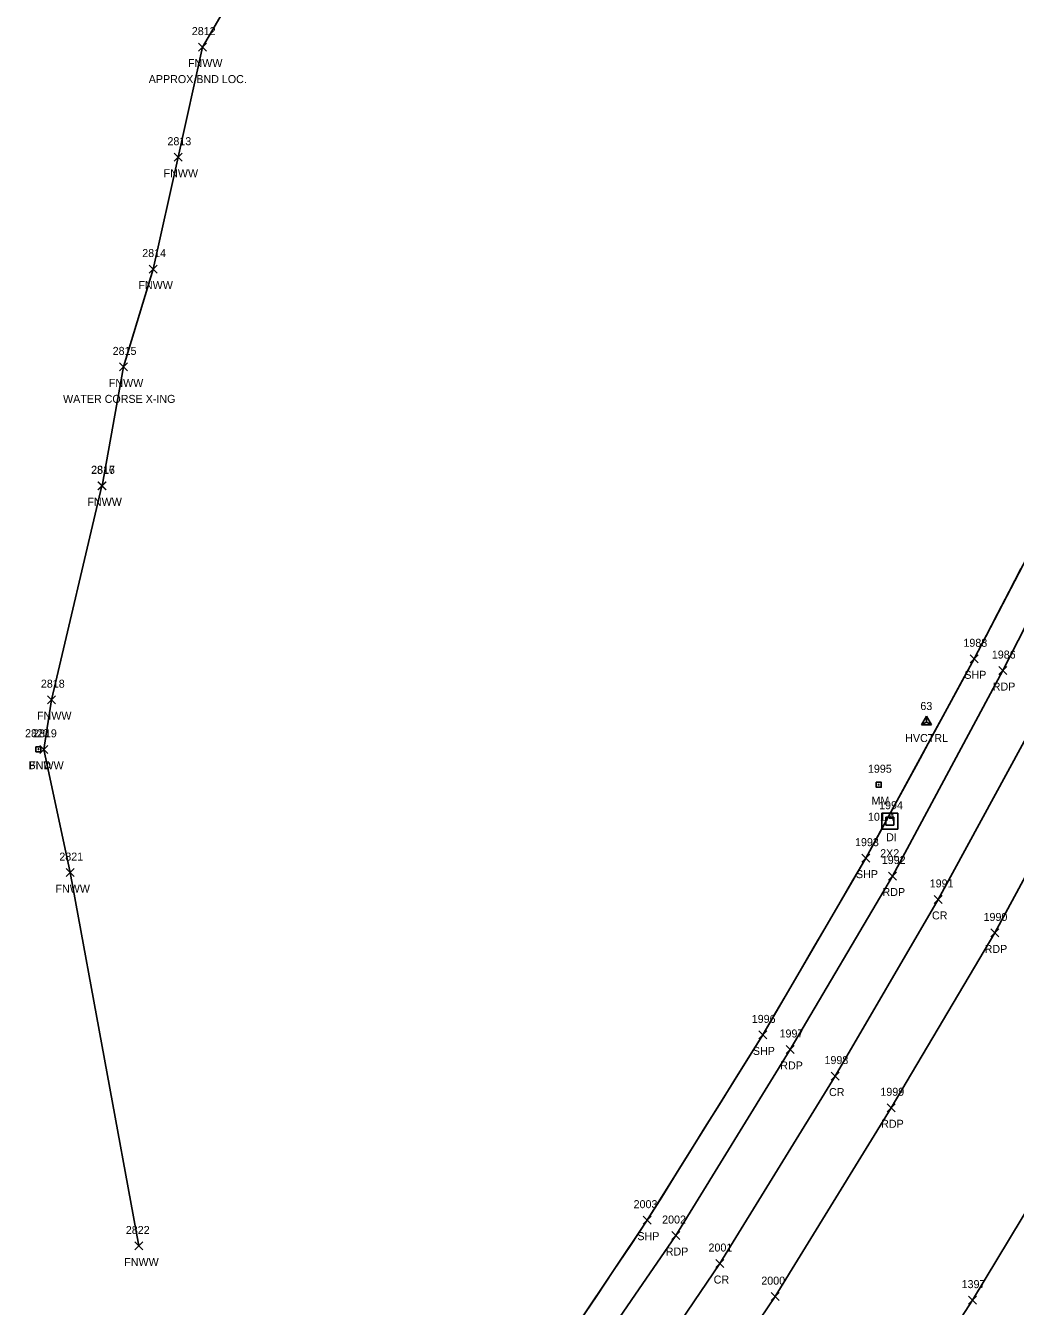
# Model space of a CAD drawing. Extents: x 1472022 to 1479249, y 777216 to 786527.
# Drawn here: x 1473093 to 1473340.4, y 778431.9 to 778752 of the extents above; entities that cross this region are included whole.
import ezdxf

# ---------------------------------------------------------------- set-up
doc = ezdxf.new("R2010")
doc.units = 0
for name, color, linetype in [('C_A', 7, 'Continuous'), ('C_I', 7, 'Continuous'), ('CPSM', 7, 'Continuous'), ('D_A', 7, 'Continuous'), ('D_C', 7, 'Continuous'), ('D_I', 7, 'Continuous'), ('DS', 7, 'Continuous'), ('L_A', 7, 'Continuous'), ('L_C', 7, 'Continuous'), ('L_I', 7, 'Continuous'), ('L_TIC', 7, 'Continuous'), ('Level 18', 7, 'Continuous'), ('LFNC', 7, 'Continuous'), ('LSOGP', 7, 'Continuous'), ('M_A', 7, 'Continuous'), ('M_I', 7, 'Continuous'), ('P_A', 7, 'Continuous'), ('P_I', 7, 'Continuous'), ('P_TIC', 7, 'Continuous'), ('PET', 7, 'Continuous'), ('PRC', 7, 'Continuous'), ('PSP', 7, 'Continuous'), ('S_A', 7, 'Continuous'), ('S_C', 7, 'Continuous'), ('S_I', 7, 'Continuous'), ('SRM', 7, 'Continuous')]:
    doc.layers.add(name, color=color, linetype=linetype)

msp = doc.modelspace()

# ---------------------------------------------------------------- linework, layer by layer
at = {"layer": 'CPSM'}
for p, q in [((1473316.9, 778577.24), (1473318.15, 778579.41)), ((1473319.4, 778577.24), (1473318.15, 778579.41)), ((1473318.15, 778577.96), (1473318.15, 778579.41)), ((1473316.9, 778577.24), (1473318.15, 778577.96)), ((1473316.9, 778577.24), (1473319.4, 778577.24)), ((1473318.15, 778577.96), (1473318.15, 778577.96)), ((1473318.15, 778577.96), (1473319.4, 778577.24))]:
    msp.add_line(p, q, dxfattribs=at)
at = {"layer": 'DS'}
for p, q in [((1473307.02, 778555.16), (1473311.02, 778555.16)), ((1473307.02, 778551.16), (1473307.02, 778555.16)), ((1473308.02, 778552.16), (1473308.02, 778554.16)), ((1473308.02, 778554.16), (1473310.02, 778554.16)), ((1473309.02, 778553.17), (1473309.02, 778553.17)), ((1473309.02, 778553.17), (1473309.02, 778553.17)), ((1473310.02, 778554.16), (1473310.02, 778552.16)), ((1473311.02, 778555.16), (1473311.02, 778551.16)), ((1473311.02, 778551.16), (1473307.02, 778551.16)), ((1473310.02, 778552.16), (1473308.02, 778552.16))]:
    msp.add_line(p, q, dxfattribs=at)
at = {"layer": 'L_TIC'}
for points in [[(1473136.27, 778745.63), (1473138.27, 778747.63)], [(1473138.27, 778745.63), (1473136.27, 778747.63)], [(1473130.18, 778718.11), (1473132.18, 778720.11)], [(1473132.18, 778718.11), (1473130.18, 778720.11)], [(1473123.89, 778690.16), (1473125.89, 778692.16)], [(1473125.89, 778690.16), (1473123.89, 778692.16)], [(1473116.49, 778665.71), (1473118.49, 778667.71)], [(1473118.49, 778665.71), (1473116.49, 778667.71)], [(1473111.13, 778636.02), (1473113.13, 778638.02)], [(1473113.13, 778636.02), (1473111.13, 778638.02)], [(1473111.14, 778635.96), (1473113.14, 778637.96)], [(1473113.14, 778635.96), (1473111.14, 778637.96)], [(1473098.55, 778582.54), (1473100.55, 778584.54)], [(1473100.55, 778582.54), (1473098.55, 778584.54)], [(1473096.59, 778570.13), (1473098.59, 778572.13)], [(1473098.59, 778570.13), (1473096.59, 778572.13)], [(1473103.16, 778539.32), (1473105.16, 778541.32)], [(1473105.16, 778539.32), (1473103.16, 778541.32)], [(1473120.35, 778446.02), (1473122.35, 778448.02)], [(1473122.35, 778446.02), (1473120.35, 778448.02)]]:
    msp.add_lwpolyline(points, dxfattribs=at)
at = {"layer": 'Level 18'}
msp.add_lwpolyline([(1473095.63, 778571.8), (1473096.88, 778571.8), (1473096.88, 778570.55), (1473095.63, 778570.55)], close=True, dxfattribs=at)
msp.add_circle((1473096.26, 778571.17), 0.0833, dxfattribs=at)
at = {"layer": 'LFNC'}
msp.add_lwpolyline([(1473307.53, 779075.77), (1473302.37, 779055.02), (1473291.71, 779013.38), (1473278.06, 778965.07), (1473248.41, 778925.8), (1473203.34, 778863.73), (1473186.54, 778833.93), (1473159.66, 778785.12), (1473137.27, 778746.63), (1473131.18, 778719.11), (1473124.89, 778691.16), (1473117.49, 778666.71), (1473112.14, 778636.96), (1473112.13, 778637.02), (1473099.55, 778583.54), (1473097.59, 778571.13), (1473104.16, 778540.32), (1473121.35, 778447.02)], dxfattribs=at)
at = {"layer": 'LSOGP'}
msp.add_lwpolyline([(1473341.77, 778616.21), (1473338.85, 778610.6), (1473335.93, 778604.99), (1473333.01, 778599.37), (1473330.09, 778593.76), (1473326.71, 778587.53), (1473323.32, 778581.3), (1473319.93, 778575.07), (1473316.55, 778568.85), (1473313.16, 778562.62), (1473309.77, 778556.39), (1473306.39, 778550.16), (1473303, 778543.94), (1473299.78, 778538.42), (1473296.56, 778532.9), (1473293.34, 778527.38), (1473290.12, 778521.86), (1473286.9, 778516.33), (1473283.69, 778510.81), (1473280.47, 778505.29), (1473277.25, 778499.77), (1473273.64, 778493.99), (1473270.03, 778488.2), (1473266.43, 778482.41), (1473262.82, 778476.62), (1473259.22, 778470.83), (1473255.61, 778465.05), (1473252, 778459.26), (1473248.4, 778453.47), (1473244.19, 778447.18), (1473239.98, 778440.88), (1473235.77, 778434.59), (1473231.56, 778428.3)], dxfattribs=at)
at = {"layer": 'P_TIC'}
for points in [[(1473329.09, 778592.76), (1473331.09, 778594.76)], [(1473331.09, 778592.76), (1473329.09, 778594.76)], [(1473336.25, 778589.82), (1473338.25, 778591.82)], [(1473338.25, 778589.82), (1473336.25, 778591.82)], [(1473302, 778542.94), (1473304, 778544.94)], [(1473304, 778542.94), (1473302, 778544.94)], [(1473308.69, 778538.48), (1473310.69, 778540.48)], [(1473310.69, 778538.48), (1473308.69, 778540.48)], [(1473320.1, 778532.63), (1473322.1, 778534.63)], [(1473322.1, 778532.63), (1473320.1, 778534.63)], [(1473334.21, 778524.25), (1473336.21, 778526.25)], [(1473336.21, 778524.25), (1473334.21, 778526.25)], [(1473276.25, 778498.77), (1473278.25, 778500.77)], [(1473278.25, 778498.77), (1473276.25, 778500.77)], [(1473283.14, 778495.13), (1473285.14, 778497.13)], [(1473285.14, 778495.13), (1473283.14, 778497.13)], [(1473294.37, 778488.48), (1473296.37, 778490.48)], [(1473296.37, 778488.48), (1473294.37, 778490.48)], [(1473308.35, 778480.56), (1473310.35, 778482.56)], [(1473310.35, 778480.56), (1473308.35, 778482.56)], [(1473247.4, 778452.47), (1473249.4, 778454.47)], [(1473249.4, 778452.47), (1473247.4, 778454.47)], [(1473254.52, 778448.63), (1473256.52, 778450.63)], [(1473256.52, 778448.63), (1473254.52, 778450.63)], [(1473265.55, 778441.63), (1473267.55, 778443.63)], [(1473267.55, 778441.63), (1473265.55, 778443.63)], [(1473279.39, 778433.36), (1473281.39, 778435.36)], [(1473281.39, 778433.36), (1473279.39, 778435.36)], [(1473328.64, 778432.49), (1473330.64, 778434.49)], [(1473330.64, 778432.49), (1473328.64, 778434.49)]]:
    msp.add_lwpolyline(points, dxfattribs=at)
at = {"layer": 'PET'}
for points in [[(1473559.55, 779345.54), (1473562.13, 779344.85), (1473559.08, 779325.48), (1473547.78, 779268.19), (1473538.56, 779219.47), (1473529.75, 779172.07), (1473520.23, 779121.16), (1473510.25, 779071.91), (1473501.42, 779032.79), (1473487.97, 778980.7), (1473476.59, 778937.83), (1473460.83, 778885.95), (1473443.7, 778834.83), (1473427.04, 778789.1), (1473404.79, 778732.7), (1473383.99, 778685.53), (1473360.34, 778636.02), (1473337.25, 778590.82), (1473309.69, 778539.48), (1473284.14, 778496.13), (1473255.52, 778449.63), (1473221.14, 778399.57)], [(1473562.13, 779344.85), (1473573.79, 779342.6), (1473588.74, 779339.91), (1473585.78, 779323.26), (1473585.84, 779321.4), (1473576.73, 779269.38), (1473567.96, 779217.59), (1473558.64, 779166.28), (1473549.3, 779116.91), (1473539.05, 779065.97), (1473530.44, 779026.51), (1473516.8, 778971.79), (1473504.7, 778929.77), (1473489.22, 778877.79), (1473471.58, 778825.33), (1473455.05, 778780.13), (1473432.04, 778722.28), (1473410.95, 778674.71), (1473387.24, 778624.16), (1473365.27, 778580.65), (1473335.21, 778525.25), (1473309.35, 778481.56), (1473280.39, 778434.36), (1473245.89, 778383.45)], [(1473301.45, 778389.87), (1473329.64, 778433.49), (1473354.46, 778474.65), (1473376.14, 778512.49), (1473401.99, 778560.39), (1473423.89, 778603.83), (1473444.72, 778647.26), (1473465.48, 778692.86), (1473485.43, 778741.59), (1473500.45, 778779.97), (1473517.46, 778826.05), (1473530.33, 778868.32), (1473543.81, 778911.93), (1473556.66, 778958.65), (1473567.98, 779002.48), (1473580.14, 779054.81), (1473589.43, 779101.31), (1473598.46, 779148.03), (1473608.13, 779200.81), (1473618, 779253.28), (1473624.21, 779286.68), (1473629.11, 779313.19), (1473632.64, 779331.64)]]:
    msp.add_lwpolyline(points, dxfattribs=at)
at = {"layer": 'PRC'}
msp.add_lwpolyline([(1473573.79, 779342.6), (1473570.41, 779324.08), (1473560.67, 779266.03), (1473551.92, 779218.05), (1473542.92, 779169.19), (1473533.33, 779119.74), (1473523.22, 779068.95), (1473514.33, 779029.92), (1473501.09, 778976.92), (1473489.49, 778934.86), (1473473.76, 778882.81), (1473456.11, 778830.27), (1473439.73, 778785.61), (1473416.92, 778727.46), (1473396.04, 778680.67), (1473372.49, 778630.75), (1473349.26, 778585.34), (1473321.1, 778533.63), (1473295.37, 778489.48), (1473266.55, 778442.63), (1473232.46, 778392.44)], dxfattribs=at)
at = {"layer": 'PSP'}
msp.add_lwpolyline([(1473559.55, 779345.54), (1473556.55, 779328.39), (1473555.66, 779326.52), (1473543.65, 779268.7), (1473533.24, 779220.88), (1473523.59, 779172.64), (1473513.3, 779122.79), (1473502.95, 779073.62), (1473494.24, 779034.96), (1473482.21, 778985.43), (1473469.56, 778939.68), (1473453.46, 778887.37), (1473437.09, 778838.65), (1473419.76, 778792.02), (1473397.52, 778736.13), (1473377.14, 778688.43), (1473353.45, 778638.67), (1473330.09, 778593.76), (1473303, 778543.94), (1473277.25, 778499.77), (1473248.4, 778453.47), (1473214.72, 778403.13)], dxfattribs=at)
at = {"layer": 'SRM'}
msp.add_lwpolyline([(1473305.61, 778562.91), (1473306.86, 778562.91), (1473306.86, 778561.66), (1473305.61, 778561.66)], close=True, dxfattribs=at)
msp.add_circle((1473306.23, 778562.29), 0.0833, dxfattribs=at)

# ---------------------------------------------------------------- texts
at = {"layer": 'C_A'}
msp.add_text('HVCTRL', height=2, dxfattribs=at).set_placement((1473312.85, 778572.96))
at = {"layer": 'C_I'}
msp.add_text('63', height=2, dxfattribs=at).set_placement((1473316.64, 778580.96))
at = {"layer": 'D_A'}
msp.add_text('DI', height=2, dxfattribs=at).set_placement((1473308.08, 778548.17))
at = {"layer": 'D_C'}
msp.add_text('2X2', height=2, dxfattribs=at).set_placement((1473306.6, 778544.17))
at = {"layer": 'D_I'}
msp.add_text('1994', height=2, dxfattribs=at).set_placement((1473306.33, 778556.17))
at = {"layer": 'L_A'}
for p in [(1473133.62, 778741.63), (1473127.53, 778714.11), (1473121.23, 778686.16), (1473113.84, 778661.71), (1473108.48, 778632.02), (1473108.49, 778631.96), (1473095.9, 778578.54), (1473093.94, 778566.13), (1473100.51, 778535.32), (1473117.69, 778442.02)]:
    msp.add_text('FNWW', height=2, dxfattribs=at).set_placement(p)
at = {"layer": 'L_C'}
for s, p in [('APPROX BND LOC.', (1473123.81, 778737.63)), ('WATER CORSE X-ING', (1473102.4, 778657.71))]:
    msp.add_text(s, height=2, dxfattribs=at).set_placement(p)
at = {"layer": 'L_I'}
for s, p in [('2812', (1473134.58, 778749.63)), ('2813', (1473128.49, 778722.11)), ('2814', (1473122.19, 778694.16)), ('2815', (1473114.8, 778669.71)), ('2816', (1473109.39, 778639.96)), ('2817', (1473109.44, 778640.02)), ('2818', (1473096.86, 778586.54)), ('2819', (1473094.89, 778574.13)), ('2821', (1473101.47, 778543.32)), ('2822', (1473118.09, 778450.02))]:
    msp.add_text(s, height=2, dxfattribs=at).set_placement(p)
at = {"layer": 'M_A'}
msp.add_text('BND', height=2, dxfattribs=at).set_placement((1473093.75, 778566.17))
at = {"layer": 'M_I'}
msp.add_text('2820', height=2, dxfattribs=at).set_placement((1473092.91, 778574.17))
at = {"layer": 'P_A'}
for s, p in [('SHP', (1473327.63, 778588.76)), ('RDP', (1473334.73, 778585.82)), ('SHP', (1473300.54, 778538.94)), ('RDP', (1473307.18, 778534.48)), ('CR', (1473319.54, 778528.63)), ('RDP', (1473332.7, 778520.25)), ('SHP', (1473274.78, 778494.77)), ('RDP', (1473281.63, 778491.13)), ('CR', (1473293.81, 778484.48)), ('RDP', (1473306.84, 778476.56)), ('SHP', (1473245.93, 778448.47)), ('RDP', (1473253.01, 778444.63)), ('CR', (1473264.99, 778437.63))]:
    msp.add_text(s, height=2, dxfattribs=at).set_placement(p)
at = {"layer": 'P_I'}
for s, p in [('1988', (1473327.4, 778596.76)), ('1986', (1473334.5, 778593.82)), ('1993', (1473300.31, 778546.94)), ('1992', (1473307, 778542.48)), ('1991', (1473318.98, 778536.63)), ('1990', (1473332.43, 778528.25)), ('1996', (1473274.5, 778502.77)), ('1997', (1473281.45, 778499.13)), ('1998', (1473292.68, 778492.48)), ('1999', (1473306.65, 778484.56)), ('2003', (1473244.98, 778456.47)), ('2002', (1473252.11, 778452.63)), ('2001', (1473263.7, 778445.63)), ('2000', (1473276.89, 778437.36)), ('1397', (1473326.95, 778436.49))]:
    msp.add_text(s, height=2, dxfattribs=at).set_placement(p)
at = {"layer": 'S_A'}
msp.add_text('MM', height=2, dxfattribs=at).set_placement((1473304.42, 778557.29))
at = {"layer": 'S_C'}
msp.add_text('101.4', height=2, dxfattribs=at).set_placement((1473303.54, 778553.29))
at = {"layer": 'S_I'}
msp.add_text('1995', height=2, dxfattribs=at).set_placement((1473303.54, 778565.29))

doc.saveas('drawing.dxf')
